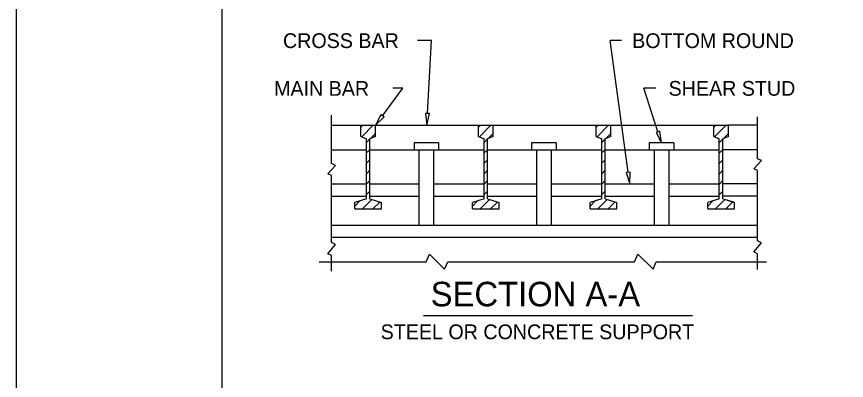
# Model space of a CAD drawing. Extents: x -24512 to -22484, y 4569 to 6351.
# Drawn here: x -24179.8 to -24010.5, y 5530.9 to 5605 of the extents above; entities that cross this region are included whole.
import ezdxf

# ---------------------------------------------------------------- set-up
doc = ezdxf.new("R2010")
doc.units = 0
for name, color, linetype in [('10', 7, 'Continuous'), ('2', 7, 'Continuous'), ('3', 7, 'Continuous'), ('4', 7, 'Continuous'), ('9', 7, 'Continuous'), ('PLT-BNDY', 7, 'Continuous')]:
    doc.layers.add(name, color=color, linetype=linetype)

# ---------------------------------------------------------------- blocks, each defined once
blk = doc.blocks.new('425IB')
at = {"layer": '3'}
for p, q in [((-0.2995, 2.972), (-0.2995, 3.427375)), ((-0.2995, 3.427375), (0.2995, 3.427375)), ((0.2995, 2.972), (0.2995, 3.427375)), ((-0.2995, 2.972), (-0.0725, 2.87125)), ((-0.0725, 0.402875), (-0.0725, 2.87125)), ((0.2995, 2.972), (0.0725, 2.87125)), ((0.0725, 0.402875), (0.0725, 2.87125)), ((-0.0725, 0.402875), (-0.548125, 0.25175)), ((0.0725, 0.402875), (0.548125, 0.25175)), ((-0.548125, 0), (-0.548125, 0.25175)), ((-0.548125, 0), (0.548125, 0)), ((0.548125, 0), (0.548125, 0.25175))]:
    blk.add_line(p, q, dxfattribs=at)
blk = doc.blocks.new('SYM045')
at = {"layer": '3'}
for p, q in [((6.1625, 35.245125), (6.239625, 35.32225)), ((6.196875, 34.85175), (6.667375, 35.32225)), ((6.542375, 34.7695), (6.76175, 34.989)), ((6.389625, 34.61675), (6.53475, 34.761875)), ((6.389625, 34.189125), (6.53475, 34.33425)), ((6.389625, 33.761375), (6.53475, 33.9065)), ((6.389625, 33.33375), (6.53475, 33.478875)), ((6.389625, 32.906), (6.53475, 33.051125)), ((6.389625, 32.478375), (6.53475, 32.6235)), ((5.914, 32.00275), (6.124875, 32.21375)), ((6.23375, 31.89475), (6.612125, 32.27325)), ((6.661375, 31.89475), (6.936625, 32.170125))]:
    blk.add_line(p, q, dxfattribs=at)

msp = doc.modelspace()

# ---------------------------------------------------------------- linework, layer by layer
at = {"layer": '10'}
msp.add_line((-24096.76, 5544.13), (-24041.87, 5544.13), dxfattribs=at)
at = {"layer": '2'}
msp.add_line((-24137.79, 5178.04), (-24137.79, 5740.63), dxfattribs=at)
at = {"layer": '4'}
for p, q in [((-24115.51, 5582.9), (-24109.52, 5582.9)), ((-24106.55, 5582.9), (-24085.52, 5582.9)), ((-24082.55, 5582.9), (-24061.52, 5582.9)), ((-24058.55, 5582.9), (-24037.52, 5582.9)), ((-24028.57, 5582.9), (-24034.55, 5582.9)), ((-24115.51, 5577.9), (-24108.4, 5577.9)), ((-24107.68, 5577.9), (-24098.68, 5577.9)), ((-24093.68, 5579.3), (-24098.68, 5579.3)), ((-24098.68, 5579.3), (-24098.68, 5577.8)), ((-24093.68, 5577.8), (-24098.68, 5577.8)), ((-24097.68, 5577.8), (-24097.68, 5562.53)), ((-24094.68, 5577.8), (-24094.68, 5562.53)), ((-24093.68, 5579.3), (-24093.68, 5577.8)), ((-24093.68, 5577.9), (-24084.4, 5577.9)), ((-24083.68, 5577.9), (-24074.69, 5577.9)), ((-24069.69, 5579.3), (-24074.69, 5579.3)), ((-24074.69, 5579.3), (-24074.69, 5577.8)), ((-24069.69, 5577.8), (-24074.69, 5577.8)), ((-24073.69, 5577.8), (-24073.69, 5562.53)), ((-24070.69, 5577.8), (-24070.69, 5562.53)), ((-24069.69, 5579.3), (-24069.69, 5577.8)), ((-24069.69, 5577.9), (-24060.4, 5577.9)), ((-24059.68, 5577.9), (-24050.69, 5577.9)), ((-24050.69, 5579.3), (-24050.69, 5577.8)), ((-24045.69, 5579.3), (-24050.69, 5579.3)), ((-24045.69, 5577.8), (-24050.69, 5577.8)), ((-24049.69, 5577.8), (-24049.69, 5562.53)), ((-24046.69, 5577.8), (-24046.69, 5562.53)), ((-24045.69, 5579.3), (-24045.69, 5577.8)), ((-24045.69, 5577.9), (-24036.4, 5577.9)), ((-24028.57, 5577.9), (-24035.68, 5577.9)), ((-24115.51, 5570.94), (-24108.4, 5570.94)), ((-24107.68, 5570.94), (-24097.68, 5570.94)), ((-24094.68, 5570.94), (-24084.4, 5570.94)), ((-24083.68, 5570.94), (-24073.69, 5570.94)), ((-24070.69, 5570.94), (-24060.4, 5570.94)), ((-24059.68, 5570.94), (-24049.69, 5570.94)), ((-24046.69, 5570.94), (-24036.4, 5570.94)), ((-24028.59, 5570.94), (-24035.68, 5570.94)), ((-24115.51, 5568.44), (-24108.4, 5568.44)), ((-24107.68, 5568.44), (-24097.68, 5568.44)), ((-24094.68, 5568.44), (-24084.4, 5568.44)), ((-24083.68, 5568.44), (-24073.69, 5568.44)), ((-24070.69, 5568.44), (-24060.4, 5568.44)), ((-24059.68, 5568.44), (-24049.69, 5568.44)), ((-24046.69, 5568.44), (-24036.4, 5568.44)), ((-24028.59, 5568.44), (-24035.68, 5568.44)), ((-24033.32, 5567.15), (-24035.01, 5567.69)), ((-24115.51, 5562.53), (-24028.59, 5562.53)), ((-24028.59, 5560.03), (-24115.51, 5560.03)), ((-24096.18, 5555.11), (-24095.54, 5556.66)), ((-24095.54, 5556.66), (-24092.44, 5553.56)), ((-24053.68, 5555.11), (-24053.04, 5556.66)), ((-24053.04, 5556.66), (-24049.93, 5553.56)), ((-24118.04, 5555.11), (-24096.18, 5555.11)), ((-24092.44, 5553.56), (-24091.8, 5555.11)), ((-24091.8, 5555.11), (-24053.68, 5555.11)), ((-24049.93, 5553.56), (-24049.29, 5555.11)), ((-24049.29, 5555.11), (-24026.76, 5555.11))]:
    msp.add_line(p, q, dxfattribs=at)
for points in [[(-24115.51, 5565.69), (-24115.51, 5572.66), (-24116.28, 5573.02), (-24114.73, 5574.72), (-24115.51, 5575.08), (-24115.51, 5584.93)], [(-24028.59, 5566.78), (-24028.59, 5573.67), (-24029.36, 5574.02), (-24027.81, 5575.73), (-24028.59, 5576.08), (-24028.59, 5584.65)], [(-24028.59, 5553.55), (-24028.59, 5556.71), (-24029.36, 5557.1), (-24027.81, 5558.98), (-24028.59, 5559.37), (-24028.59, 5566.78)], [(-24115.51, 5553.19), (-24115.51, 5556.35), (-24116.28, 5556.74), (-24114.73, 5558.62), (-24115.51, 5559.01), (-24115.51, 5565.69)]]:
    msp.add_lwpolyline(points, dxfattribs=at)
at = {"layer": '9'}
for p, q in [((-24095.11, 5600.19), (-24098, 5600.19)), ((-24095.11, 5600.19), (-24097.43, 5600.19)), ((-24095.91, 5585.29), (-24095.11, 5600.19)), ((-24056.33, 5600.19), (-24058.66, 5600.19)), ((-24055.01, 5573.32), (-24058.66, 5600.19)), ((-24105.12, 5584.82), (-24100.93, 5590.47)), ((-24100.93, 5590.47), (-24103, 5590.47)), ((-24049.35, 5590.47), (-24051.77, 5590.47)), ((-24048.92, 5581.59), (-24051.77, 5590.47))]:
    msp.add_line(p, q, dxfattribs=at)
for points in [[(-24104.8, 5584.59), (-24105.44, 5585.06), (-24106.55, 5582.9)], [(-24095.51, 5585.27), (-24096.31, 5585.32), (-24096.04, 5582.9)], [(-24048.54, 5581.71), (-24049.3, 5581.46), (-24048.19, 5579.3)], [(-24054.61, 5573.37), (-24055.4, 5573.27), (-24054.68, 5570.94)]]:
    msp.add_lwpolyline(points, close=True, dxfattribs=at)
at = {"layer": 'PLT-BNDY'}
msp.add_lwpolyline([(-24179.75, 5757.04), (-23338.75, 5757.04), (-23338.75, 5163.04), (-24179.75, 5163.04)], close=True, dxfattribs=at)

# ---------------------------------------------------------------- block references
at = {"layer": '3', "xscale": 4.959842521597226, "yscale": 4.959842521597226}
for name, p in [('425IB', (-24108.04, 5565.9)), ('SYM045', (-24140.09, 5407.7)), ('SYM045', (-24116.09, 5407.7)), ('425IB', (-24084.04, 5565.9)), ('SYM045', (-24092.09, 5407.7)), ('425IB', (-24060.04, 5565.9)), ('SYM045', (-24068.09, 5407.7)), ('425IB', (-24036.04, 5565.9))]:
    msp.add_blockref(name, p, dxfattribs=at)

# ---------------------------------------------------------------- texts
at = {"layer": '9'}
for s, height, p in [('CROSS BAR', 3, (-24125.41, 5598.64)), ('BOTTOM ROUND', 2.9999, (-24054.18, 5598.64)), ('MAIN BAR', 3, (-24127.23, 5588.9)), ('SHEAR STUD', 3, (-24046.75, 5588.92)), ('SECTION A-A', 5, (-24095.28, 5546.01)), ('STEEL OR CONCRETE SUPPORT', 2.9999, (-24105.49, 5539.32))]:
    msp.add_text(s, height=height, dxfattribs=at).set_placement(p)

doc.saveas('drawing.dxf')
